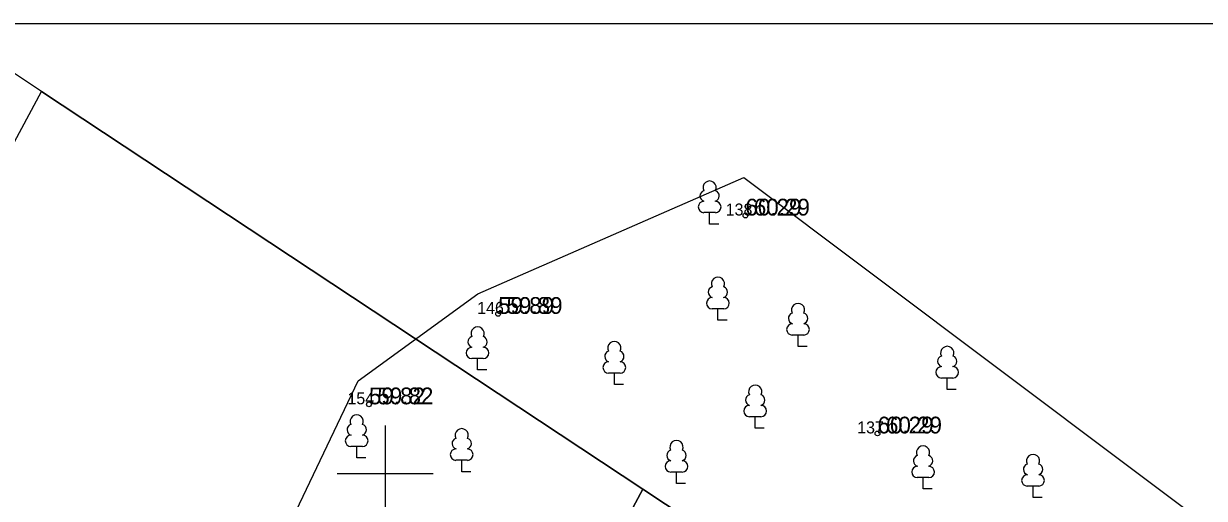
# Model space of a CAD drawing. Extents: x 640891 to 641083, y 6456526 to 6456669.
# Drawn here: x 640934.89 to 640984.23, y 6456648.96 to 6456668.78 of the extents above; entities that cross this region are included whole.
import ezdxf

# ---------------------------------------------------------------- set-up
doc = ezdxf.new("R2010")
doc.units = 0
for name, color, linetype in [('KORGUS', 7, 'Continuous'), ('MOOTKORG', 7, 'Continuous'), ('MOOTMPUNKT', 7, 'Continuous'), ('MOOTNR', 7, 'Continuous'), ('MOOTPIIR', 7, 'Continuous'), ('PIIR', 7, 'Continuous'), ('PUU', 7, 'Continuous'), ('VORK', 7, 'Continuous'), ('VORMISTUS', 7, 'Continuous')]:
    doc.layers.add(name, color=color, linetype=linetype)

msp = doc.modelspace()

# ---------------------------------------------------------------- linework, layer by layer
at = {"layer": 'KORGUS'}
for centre in [(640965.053, 6456660.767), (640954.719, 6456656.662), (640949.323, 6456652.887), (640970.573, 6456651.671)]:
    msp.add_circle(centre, 0.1, dxfattribs=at)
at = {"layer": 'MOOTMPUNKT'}
for centre in [(640965.053, 6456660.767), (640954.719, 6456656.662), (640949.323, 6456652.887), (640970.573, 6456651.671)]:
    msp.add_circle(centre, 0.1, dxfattribs=at)
at = {"layer": 'MOOTPIIR'}
msp.add_lwpolyline([(640924.706, 6456598.502), (640938.233, 6456631.58), (640948.873, 6456653.866), (640953.873, 6456657.504), (640964.983, 6456662.356), (640986.497, 6456646.235), (640995.587, 6456643.81), (640989.565, 6456627.418), (640994.744, 6456619.938), (640993.953, 6456602.696)], dxfattribs=at)
at = {"layer": 'PIIR'}
msp.add_lwpolyline([(641039.59, 6456660.086), (641000.58, 6456623), (640985.89, 6456632.73), (640960.76, 6456649.34), (640935.64, 6456665.95), (640931.367, 6456668.776)], dxfattribs=at)
for points in [[(640930.79, 6456593.51), (640904.36, 6456607.7), (640935.64, 6456665.95), (640960.76, 6456649.34)], [(640957.22, 6456579.32), (640930.79, 6456593.51), (640960.76, 6456649.34), (640985.89, 6456632.73)]]:
    msp.add_lwpolyline(points, close=True, dxfattribs=at)
at = {"layer": 'PUU'}
for p, q in [((640963.798, 6456660.887), (640963.318, 6456660.887)), ((640963.558, 6456660.412), (640963.558, 6456660.887)), ((640963.938, 6456660.412), (640963.558, 6456660.412)), ((640964.144, 6456656.873), (640963.664, 6456656.873)), ((640963.904, 6456656.398), (640963.904, 6456656.873)), ((640964.284, 6456656.398), (640963.904, 6456656.398)), ((640967.492, 6456655.776), (640967.012, 6456655.776)), ((640967.252, 6456655.301), (640967.252, 6456655.776)), ((640967.632, 6456655.301), (640967.252, 6456655.301)), ((640954.102, 6456654.794), (640953.622, 6456654.794)), ((640953.862, 6456654.319), (640953.862, 6456654.794)), ((640954.242, 6456654.319), (640953.862, 6456654.319)), ((640959.816, 6456654.187), (640959.336, 6456654.187)), ((640959.576, 6456653.712), (640959.576, 6456654.187)), ((640973.725, 6456653.985), (640973.245, 6456653.985)), ((640973.485, 6456653.51), (640973.485, 6456653.985)), ((640959.956, 6456653.712), (640959.576, 6456653.712)), ((640973.865, 6456653.51), (640973.485, 6456653.51)), ((640965.703, 6456652.368), (640965.223, 6456652.368)), ((640965.463, 6456651.893), (640965.463, 6456652.368)), ((640965.843, 6456651.893), (640965.463, 6456651.893)), ((640949.052, 6456651.126), (640948.572, 6456651.126)), ((640948.812, 6456650.651), (640948.812, 6456651.126)), ((640949.192, 6456650.651), (640948.812, 6456650.651)), ((640953.438, 6456650.549), (640952.958, 6456650.549)), ((640953.198, 6456650.074), (640953.198, 6456650.549)), ((640953.578, 6456650.074), (640953.198, 6456650.074)), ((640962.413, 6456650.058), (640961.933, 6456650.058)), ((640962.173, 6456649.583), (640962.173, 6456650.058)), ((640962.553, 6456649.583), (640962.173, 6456649.583)), ((640972.715, 6456649.827), (640972.235, 6456649.827)), ((640972.475, 6456649.352), (640972.475, 6456649.827)), ((640977.311, 6456649.473), (640976.831, 6456649.473)), ((640977.071, 6456648.998), (640977.071, 6456649.473)), ((640972.855, 6456649.352), (640972.475, 6456649.352)), ((640977.451, 6456648.998), (640977.071, 6456648.998))]:
    msp.add_line(p, q, dxfattribs=at)
for centre, radius, start, end in [((640963.558, 6456661.932), 0.277, 332.5799, 207.4201), ((640963.388, 6456661.584), 0.233, 109.0217, 253.1415), ((640963.728, 6456661.584), 0.233, 286.8508, 70.9859), ((640963.321, 6456661.124), 0.238, 90.0016, 269.3953), ((640963.795, 6456661.124), 0.238, 270.6047, 89.9984), ((640963.734, 6456657.57), 0.233, 109.0217, 253.1415), ((640963.904, 6456657.918), 0.277, 332.5799, 207.4201), ((640964.074, 6456657.57), 0.233, 286.8508, 70.9859), ((640963.667, 6456657.11), 0.238, 90.0016, 269.3953), ((640964.142, 6456657.11), 0.238, 270.6047, 89.9984), ((640967.252, 6456656.821), 0.277, 332.5799, 207.4201), ((640967.082, 6456656.473), 0.233, 109.0217, 253.1415), ((640967.422, 6456656.473), 0.233, 286.8508, 70.9859), ((640953.862, 6456655.839), 0.277, 332.5799, 207.4201), ((640967.014, 6456656.013), 0.238, 90.0016, 269.3953), ((640967.489, 6456656.013), 0.238, 270.6047, 89.9984), ((640953.692, 6456655.491), 0.233, 109.0217, 253.1415), ((640954.032, 6456655.491), 0.233, 286.8508, 70.9859), ((640959.576, 6456655.232), 0.277, 332.5799, 207.4201), ((640973.485, 6456655.03), 0.277, 332.5799, 207.4201), ((640953.624, 6456655.031), 0.238, 90.0016, 269.3953), ((640954.099, 6456655.031), 0.238, 270.6047, 89.9984), ((640959.406, 6456654.885), 0.233, 109.0217, 253.1415), ((640959.746, 6456654.885), 0.233, 286.8508, 70.9859), ((640973.315, 6456654.683), 0.233, 109.0217, 253.1415), ((640973.655, 6456654.683), 0.233, 286.8508, 70.9859), ((640959.338, 6456654.425), 0.238, 90.0016, 269.3953), ((640959.813, 6456654.425), 0.238, 270.6047, 89.9984), ((640973.248, 6456654.223), 0.238, 90.0016, 269.3953), ((640973.723, 6456654.223), 0.238, 270.6047, 89.9984), ((640965.463, 6456653.413), 0.277, 332.5799, 207.4201), ((640965.225, 6456652.606), 0.238, 90.0016, 269.3953), ((640965.293, 6456653.066), 0.233, 109.0217, 253.1415), ((640965.633, 6456653.066), 0.233, 286.8508, 70.9859), ((640965.7, 6456652.606), 0.238, 270.6047, 89.9984), ((640948.812, 6456652.171), 0.277, 332.5799, 207.4201), ((640948.641, 6456651.824), 0.233, 109.0217, 253.1415), ((640948.982, 6456651.824), 0.233, 286.8508, 70.9859), ((640953.198, 6456651.594), 0.277, 332.5799, 207.4201), ((640948.574, 6456651.364), 0.238, 90.0016, 269.3953), ((640949.049, 6456651.364), 0.238, 270.6047, 89.9984), ((640953.028, 6456651.246), 0.233, 109.0217, 253.1415), ((640953.368, 6456651.246), 0.233, 286.8508, 70.9859), ((640962.173, 6456651.103), 0.277, 332.5799, 207.4201), ((640952.96, 6456650.786), 0.238, 90.0016, 269.3953), ((640953.435, 6456650.786), 0.238, 270.6047, 89.9984), ((640962.003, 6456650.755), 0.233, 109.0217, 253.1415), ((640962.343, 6456650.755), 0.233, 286.8508, 70.9859), ((640972.475, 6456650.872), 0.277, 332.5799, 207.4201), ((640961.935, 6456650.295), 0.238, 90.0016, 269.3953), ((640962.41, 6456650.295), 0.238, 270.6047, 89.9984), ((640972.305, 6456650.524), 0.233, 109.0217, 253.1415), ((640972.645, 6456650.524), 0.233, 286.8508, 70.9859), ((640976.901, 6456650.171), 0.233, 109.0217, 253.1415), ((640977.071, 6456650.518), 0.277, 332.5799, 207.4201), ((640977.241, 6456650.171), 0.233, 286.8508, 70.9859), ((640972.238, 6456650.064), 0.238, 90.0016, 269.3953), ((640972.713, 6456650.064), 0.238, 270.6047, 89.9984), ((640976.833, 6456649.711), 0.238, 90.0016, 269.3953), ((640977.308, 6456649.711), 0.238, 270.6047, 89.9984)]:
    msp.add_arc(centre, radius, start, end, dxfattribs=at)
at = {"layer": 'VORK'}
for p, q in [((640950, 6456652), (640950, 6456648)), ((640948, 6456650), (640952, 6456650))]:
    msp.add_line(p, q, dxfattribs=at)
at = {"layer": 'VORMISTUS'}
msp.add_line((640890.598, 6456668.776), (641082.733, 6456668.776), dxfattribs=at)

# ---------------------------------------------------------------- texts
at = {"layer": 'KORGUS'}
for s, p in [('60.29', (640965.403, 6456660.767)), ('59.89', (640955.069, 6456656.662)), ('59.82', (640949.673, 6456652.887)), ('60.29', (640970.923, 6456651.671))]:
    msp.add_text(s, height=0.7, dxfattribs=at).set_placement(p)
at = {"layer": 'MOOTKORG'}
for s, p in [('60.29', (640965.053, 6456660.767)), ('59.89', (640954.719, 6456656.662)), ('59.82', (640949.323, 6456652.887)), ('60.29', (640970.573, 6456651.671))]:
    msp.add_text(s, height=0.7, dxfattribs=at).set_placement(p)
at = {"layer": 'MOOTNR'}
for s, p in [('138', (640964.228, 6456660.767)), ('146', (640953.845, 6456656.662)), ('154', (640948.423, 6456652.887)), ('137', (640969.723, 6456651.671))]:
    msp.add_text(s, height=0.5, dxfattribs=at).set_placement(p)

doc.saveas('drawing.dxf')
